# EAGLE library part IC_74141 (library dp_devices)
BCD to decimal decoder
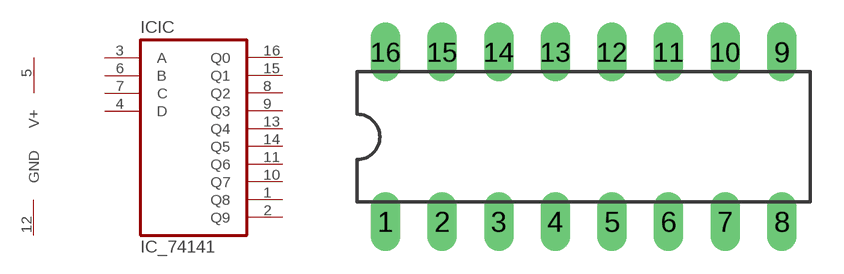
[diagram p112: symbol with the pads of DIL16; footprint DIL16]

Designator prefix IC; gates IC=74141 SUPPLY=SUPPLY

## IC_74141-DIP-16  [DIL16]
1  IC:Q8  out
2  IC:Q9  out
3  IC:A  in
4  IC:D  in
5  SUPPLY:V+  sup
6  IC:B  in
7  IC:C  in
8  IC:Q2  out
9  IC:Q3  out
10  IC:Q7  out
11  IC:Q6  out
12  SUPPLY:GND  sup
13  IC:Q4  out
14  IC:Q5  out
15  IC:Q1  out
16  IC:Q0  out

## Footprint DIL16 (pad centres in mm)
DIL-16
drill 0.813 long: 1 -8.89,-3.81; 2 -6.35,-3.81; 3 -3.81,-3.81; 4 -1.27,-3.81; 5 1.27,-3.81; 6 3.81,-3.81; 7 6.35,-3.81; 8 8.89,-3.81; 9 8.89,3.81; 10 6.35,3.81; 11 3.81,3.81; 12 1.27,3.81; 13 -1.27,3.81; 14 -3.81,3.81; 15 -6.35,3.81; 16 -8.89,3.81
